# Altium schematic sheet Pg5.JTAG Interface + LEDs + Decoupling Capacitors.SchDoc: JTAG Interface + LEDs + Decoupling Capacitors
size 431 x 279 mm; Date: Not shown in title block; ApprovedBy: Not shown in title block; CheckedBy: Not shown in title block; Author: Not shown in title block; CompanyName: Not shown in title block; Engineer: Not shown in title block; Organization: Not shown in title block; Address1: Not shown in title block; Address2: Not shown in title block; Address3: Not shown in title block; Address4: Not shown in title block; DocumentNumber: 5; Revision: Use project parameter SCH_Rev; SheetNumber: 5; SheetTotal: 8; PageSetup: Record=PageOptions|CenterHorizontal=True|CenterVertical=True|PrintScale=1.00|XCorrection=1.00|YCorrection=1.00|PrintKind=0|BorderSize=5000000|LeftOffset=0|BottomOffset=0|Orientation=2|PaperLength=1000|PaperWidth=1000|Scale=100|PaperSource=15|PrintQuality=600|MediaType=1|DitherType=10|PaperKind=Letter|PrintScaleMode=1
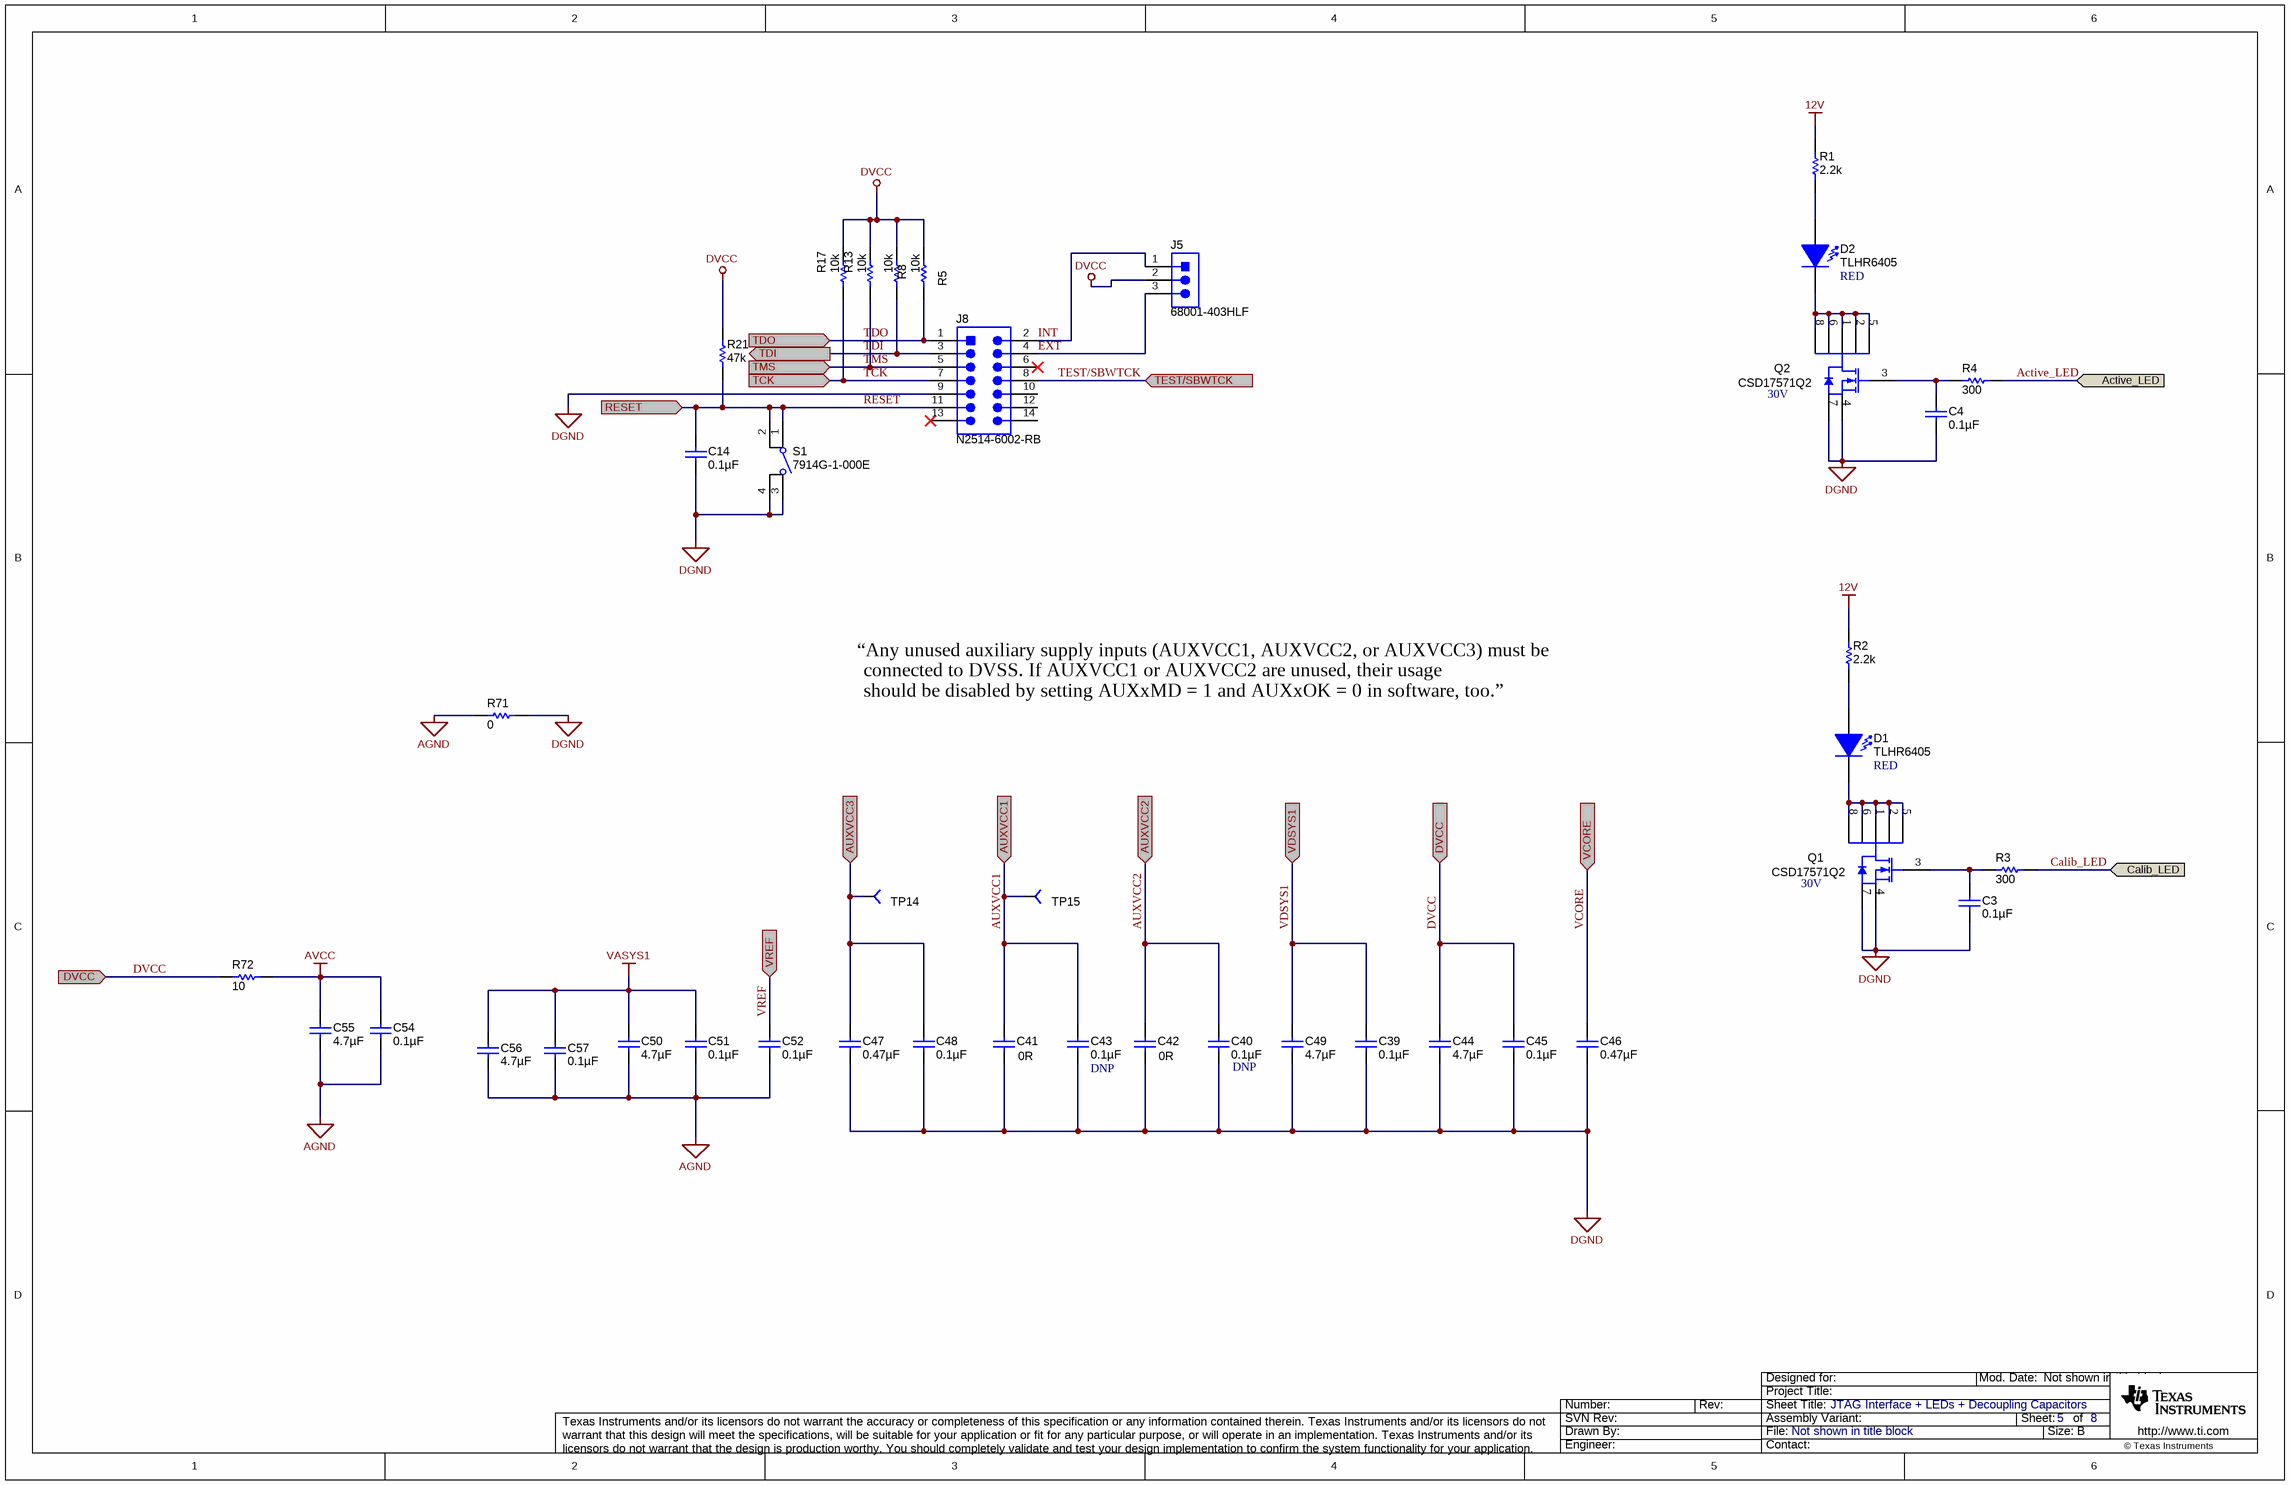
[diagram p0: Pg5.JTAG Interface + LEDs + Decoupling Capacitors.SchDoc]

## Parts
C3  ValueDisplayed: 0.1µF  [0603]  (hidden comment: 06033C104JAT2A)
C4  ValueDisplayed: 0.1µF  [0603]  (hidden comment: 06033C104JAT2A)
C14  ValueDisplayed: 0.1µF  [0603]  (hidden comment: 06033C104JAT2A)
C39  ValueDisplayed: 0.1µF  [0603]  (hidden comment: 06033C104JAT2A)
C40  ValueDisplayed: 0.1µF  Fitted: DNP  [0603]  (hidden comment: 06033C104JAT2A)
C41  value 0R  [0603]  (hidden comment: CRCW06030000Z0EA)
C42  value 0R  [0603]  (hidden comment: CRCW06030000Z0EA)
C43  ValueDisplayed: 0.1µF  Fitted: DNP  [0603]  (hidden comment: 06033C104JAT2A)
C44  ValueDisplayed: 4.7µF  [0603]  (hidden comment: 0603ZD475KAT2A)
C45  ValueDisplayed: 0.1µF  [0603]  (hidden comment: 06033C104JAT2A)
C46  ValueDisplayed: 0.47µF  [0603]  (hidden comment: GRM188R71E474KA12J)
C47  ValueDisplayed: 0.47µF  [0603]  (hidden comment: GRM188R71E474KA12J)
C48  ValueDisplayed: 0.1µF  [0603]  (hidden comment: 06033C104JAT2A)
C49  ValueDisplayed: 4.7µF  [0603]  (hidden comment: 0603ZD475KAT2A)
C50  ValueDisplayed: 4.7µF  [0603]  (hidden comment: 0603ZD475KAT2A)
C51  ValueDisplayed: 0.1µF  [0603]  (hidden comment: 06033C104JAT2A)
C52  ValueDisplayed: 0.1µF  [0603]  (hidden comment: 06033C104JAT2A)
C54  ValueDisplayed: 0.1µF  [0603]  (hidden comment: 06033C104JAT2A)
C55  ValueDisplayed: 4.7µF  [0603]  (hidden comment: 0603ZD475KAT2A)
C56  ValueDisplayed: 4.7µF  [0603]  (hidden comment: 0603ZD475KAT2A)
C57  ValueDisplayed: 0.1µF  [0603]  (hidden comment: 06033C104JAT2A)
D1  TLHR6405  value RED  [LED_5MM]
D2  TLHR6405  value RED  [LED_5MM]
J5  68001-403HLF  [HDR1X3]
J8  N2514-6002-RB  [3M_N2514-6002-RB]
Q1  CSD17571Q2  value 30V  [SON_CSD17571Q2]
Q2  CSD17571Q2  value 30V  [SON_CSD17571Q2]
R1  value 2.2k  [0603]  (hidden comment: CRCW06032K20JNEA)
R2  value 2.2k  [0603]  (hidden comment: CRCW06032K20JNEA)
R3  value 300  [0603]  (hidden comment: CRCW0603300RJNEA)
R4  value 300  [0603]  (hidden comment: CRCW0603300RJNEA)
R5  value 10k  [0603]  (hidden comment: CRCW060310K0JNEA)
R8  value 10k  [0603]  (hidden comment: CRCW060310K0JNEA)
R13  value 10k  [0603]  (hidden comment: CRCW060310K0JNEA)
R17  value 10k  [0603]  (hidden comment: CRCW060310K0JNEA)
R21  value 47k  [0603]  (hidden comment: CRCW060347K0JNEA)
R71  value 0  [0805_HV]  (hidden comment: CRCW08050000Z0EA)
R72  value 10  [0805_HV]  (hidden comment: CRCW080510R0JNEA)
S1  7914G-1-000E  [SW_7914G-1-000E]
TP14  TP-040_RND  [TP_25MIL-SMT]  (value not drawn)
TP15  TP-040_RND  [TP_25MIL-SMT]  (value not drawn)

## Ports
Active_LED (in), AUXVCC1, AUXVCC2, AUXVCC3, Calib_LED (in), DVCC, RESET, TCK, TDI (out), TDO, TEST/SBWTCK, TMS, VCORE, VDSYS1, VREF

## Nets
12V: R1.2 R2.2
AGND: C50.2 C51.2 C52.2 C54.2 C55.2 C56.2 C57.2 R71.1
AVCC: C54.1 C55.1 R72.2
DGND: C3.2 C4.2 C14.1 C39.2 C40.2 C41.2 C42.2 C43.2 C44.2 C45.2 C46.2 C47.2 C48.2 C49.2 J8.9 Q1.4(S) Q1.7(S) Q2.4(S) Q2.7(S) R71.2 S1.3 S1.4
DVCC: C44.1 C45.1 J5.2 R5.1 R8.1 R13.1 R17.1 R21.2 R72.1 ; port DVCC
VASYS1: C50.1 C51.1 C56.1 C57.1
Active_LED: R4.1 ; port Active_LED
AUXVCC1: C41.1 C43.1 TP15.1 ; port AUXVCC1
AUXVCC2: C40.1 C42.1 ; port AUXVCC2
AUXVCC3: C47.1 C48.1 TP14.1 ; port AUXVCC3
Calib_LED: R3.1 ; port Calib_LED
EXT: J5.3 J8.4
INT: J5.1 J8.2
RESET: C14.2 J8.11 R21.1 S1.1 S1.2 ; port RESET
TCK: J8.7 R17.2 ; port TCK
TDI: J8.3 R8.2 ; port TDI
TDO: J8.1 R5.2 ; port TDO
TEST/SBWTCK: J8.8 ; port TEST/SBWTCK
TMS: J8.5 R13.2 ; port TMS
VCORE: C46.1 ; port VCORE
VDSYS1: C39.1 C49.1 ; port VDSYS1
VREF: C52.1 ; port VREF
NetC3_1: C3.1 Q1.3(G) R3.2
NetC4_1: C4.1 Q2.3(G) R4.2
NetD1_1: D1.1(K) Q1.1(D) Q1.2(D) Q1.5(D) Q1.6(D) Q1.8(D)
NetD1_2: D1.2(A) R2.1
NetD2_1: D2.1(K) Q2.1(D) Q2.2(D) Q2.5(D) Q2.6(D) Q2.8(D)
NetD2_2: D2.2(A) R1.1

Not connected (* = marked no-connect by the designer): J8 6* 10 12 13* 14

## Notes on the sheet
- “Any unused auxiliary supply inputs (AUXVCC1, AUXVCC2, or AUXVCC3) must be
- connected to DVSS. If AUXVCC1 or AUXVCC2 are unused, their usage
- should be disabled by setting AUXxMD = 1 and AUXxOK = 0 in software, too.”

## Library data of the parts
C3 C4 C14 C39 C40 C43 C45 C48 C51 C52 C54 C57 = 06033C104JAT2A: CAP, CERM, 0.1uF, 25V, +/-5%, X7R, 0603; Manufacturer: AVX; Polarized: N; CompType: Capacitor; U/M: EA; Cap_F: 0.0000001; Tolerance_%: 5; ESR_Ohm: 0.05; Value1: 0.05 ohm; VDC_V: 25; TaMin_C: -55; TaMax_C: 125
C41 C42 = 0603ZD475KAT2A: RES 0.0 OHM 1/10W JUMP 0603 SMD; Manufacturer: Vishay-Dale; CompType: Capacitor; U/M: EA; Cap_F: 0.0000047; Value1: Unknown; TaMin_C: -55; TaMax_C: 85
C44 C49 C50 C55 C56 = 0603ZD475KAT2A: CAP, CERM, 4.7uF, 10V, +/-10%, X5R, 0603; Manufacturer: AVX; Polarized: N; CompType: Capacitor; U/M: EA; Cap_F: 0.0000047; Tolerance_%: 10; Value1: Unknown; TaMin_C: -55; TaMax_C: 85
C46 C47 = GRM188R71E474KA12D: CAP, CERM, 0.47uF, 25V, +/-10%, X7R, 0603; Manufacturer: MuRata; Polarized: N; CompType: Capacitor; U/M: EA; Cap_F: 0.00000047; Tolerance_%: 10; Value1: Unknown; VDC_V: 25; TaMin_C: -55; TaMax_C: 125
D1 D2 = TLHR6405: LED, 5MM, RED, TH; Manufacturer: VISHAY; SymbolCreator: x0199378
J5 = 009155003301006: 3 pin berger; Manufacturer: FCI; SymbolCreator: a0799628; CompType: Connector; U/M: EA
J8 = 0015912140: Header, 7x2, 100mil, SMT; Manufacturer: Molex; SymbolCreator: a0412235; U/M: EA
Q1 Q2 = CSD17571Q2: MOSFET, N-CH, 30V, 22A, SON 2X2 MM; Manufacturer: TEXAS INSTRUMENTS; CompType: POWER MOSFET
R1 R2 = CRCW06032K20JNEA: RES, 2.2k ohm, 5%, 0.1W, 0603; Manufacturer: Vishay-Dale; CompType: Resistor; Res_ohm: 2200; Value_Code: 2k20; Tolerance_%: 5; Power_W: 0.1; VDC_V: 75; TempCo: 200 ppm/C; EIA_Code: E24; U/M: EA
R3 R4 = CRCW0603300RJNEA: RES, 300 ohm, 5%, 0.1W, 0603; Manufacturer: Vishay-Dale; CompType: Resistor; Value_Code: 300R; Tolerance_%: 5; Power_W: 0.1; VDC_V: 75; TempCo: 200 ppm/C; EIA_Code: E24; U/M: EA
R5 R8 R13 R17 = RNCF0603TKY10K0: RES 10K OHM 1/10W 5% 0603 SMD; Manufacturer: Vishay-Dale; CompType: Resistor; Res_ohm: 10000; Value_Code: 10k0; Tolerance_%: 0.01; Value1: 0.01%; Power_W: 0.063; Value2: 0.063W; VDC_V: 50; TempCo: 5 ppm/C; U/M: EA
R21 = CRCW060347K0JNEA: RES, 47k ohm, 5%, 0.1W, 0603; Manufacturer: Vishay-Dale; CompType: Resistor; Res_ohm: 47000; Value_Code: 47k0; Tolerance_%: 5; Power_W: 0.1; VDC_V: 75; TempCo: 200 ppm/C; EIA_Code: E24; U/M: EA
R71 = CRCW0805330KJNEA: RES, 0 ohm, 5%, 0.125W, 0805; Manufacturer: Vishay-Dale; CompType: Resistor; Tolerance_%: 5; Power_W: 0.125; VDC_V: 150; TempCo: 200 ppm/C; EIA_Code: E24; U/M: EA
R72 = CRCW080510R0JNEA: RES, 10 ohm, 5%, 0.125W, 0805; Manufacturer: Vishay-Dale; CompType: Resistor; Value_Code: 10R0; Tolerance_%: 5; Power_W: 0.125; VDC_V: 150; TempCo: 200 ppm/C; EIA_Code: E24; U/M: EA
S1 = 7914G-1-000E: Switch, Tactile, SPST-NO, 0.1A, 16V, SMT; Manufacturer: Bourns; SymbolCreator: a0412235; VDC_V: 16; SwitchFunction: Off-Mom; PositionCount: 1; CurrentRating_mA: 100
TP14 TP15 = TP-040_RND: Test Point, O.040 Hole; Manufacturer: STD; Value: STD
